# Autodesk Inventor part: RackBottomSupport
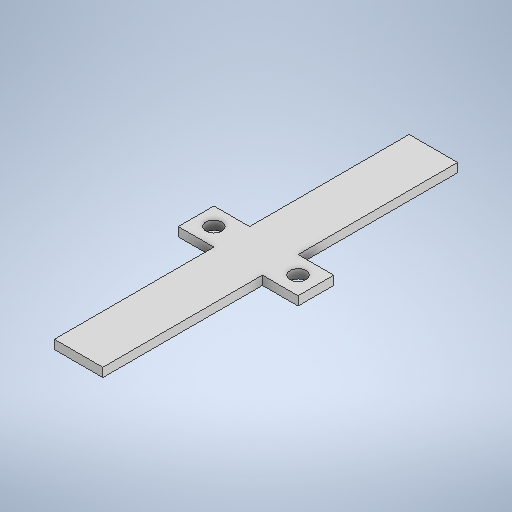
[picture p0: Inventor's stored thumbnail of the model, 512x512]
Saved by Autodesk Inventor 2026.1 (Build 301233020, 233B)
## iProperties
Created: 2026-11
Part Number: RackBottomSupport
Material: Generic
Document SubType Name: Modeling
Designer: hp
Density: 1 g/cm^3
Appearance: Default
Author: hp
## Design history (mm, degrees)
sketch "Sketch1"
  geometry: L1 (-13.134, 99.677)-(14.066, 99.677); L2 (14.066, 99.677)-(14.066, -99.323); L3 (14.066, -99.323)-(-13.134, -99.323); L4 (-13.134, -99.323)-(-13.134, 99.677); L5 (-3.134, 88.677)-(4.066, 88.677); L6 (-3.134, -88.323)-(-3.134, 88.677); L7 (4.066, 88.677)-(4.066, -88.323); L8 (4.066, -88.323)-(-3.134, -88.323); L9 (14.066, 10.177)-(34.066, 10.177); L10 (34.066, 10.177)-(34.066, -9.823); L11 (34.066, -9.823)-(14.066, -9.823); L12 (14.066, -9.823)-(14.066, 10.177); L13 (-13.134, 10.177)-(-33.134, 10.177); L14 (-33.134, 10.177)-(-33.134, -9.823); L15 (-33.134, -9.823)-(-13.134, -9.823); L16 (-13.134, -9.823)-(-13.134, 10.177); C1 r 3.75 at (24.066, 0.177); C2 r 3.75 at (-23.134, 0.177); 8 further points
  constraints: 32 end point, 6 parallel, 5 midpoint, 3 horizontal, 3 perpendicular, 3 point on line, 2 centre point, 2 horizontal alignment, 1 collinear, 1 vertical alignment
  dimensions: "d0" = 10 distance between parallel lines of L7 L2; "d1" = 11 distance between parallel lines of L8 L3; "d2" = 20 distance of L10.end L11.end; "d3" = 20 distance of L9.end L10.end; "d4" = 20 distance of L14.end L15.end (= d2); "d7" = 7.5 diameter of C1; "d8" = 7.5 diameter of C2
extrude "Extrusion1" new body sketch "Sketch1" distance "d5" = 5; taper "d6" = 0 deg
sketch "Sketch2"
  geometry: 2 further points
hole "Hole1" sketch "Sketch2" at (23.134, -0.177), (-24.066, -0.177) diameter "d9" = 9; stored, may be unused: countersink angle "d13" = 90 deg, drill point angle "d15" = 0 deg; dims "d10" = 6, "d11" = 4, "d12" = 2, "d14" = 8
body "Solid1"
